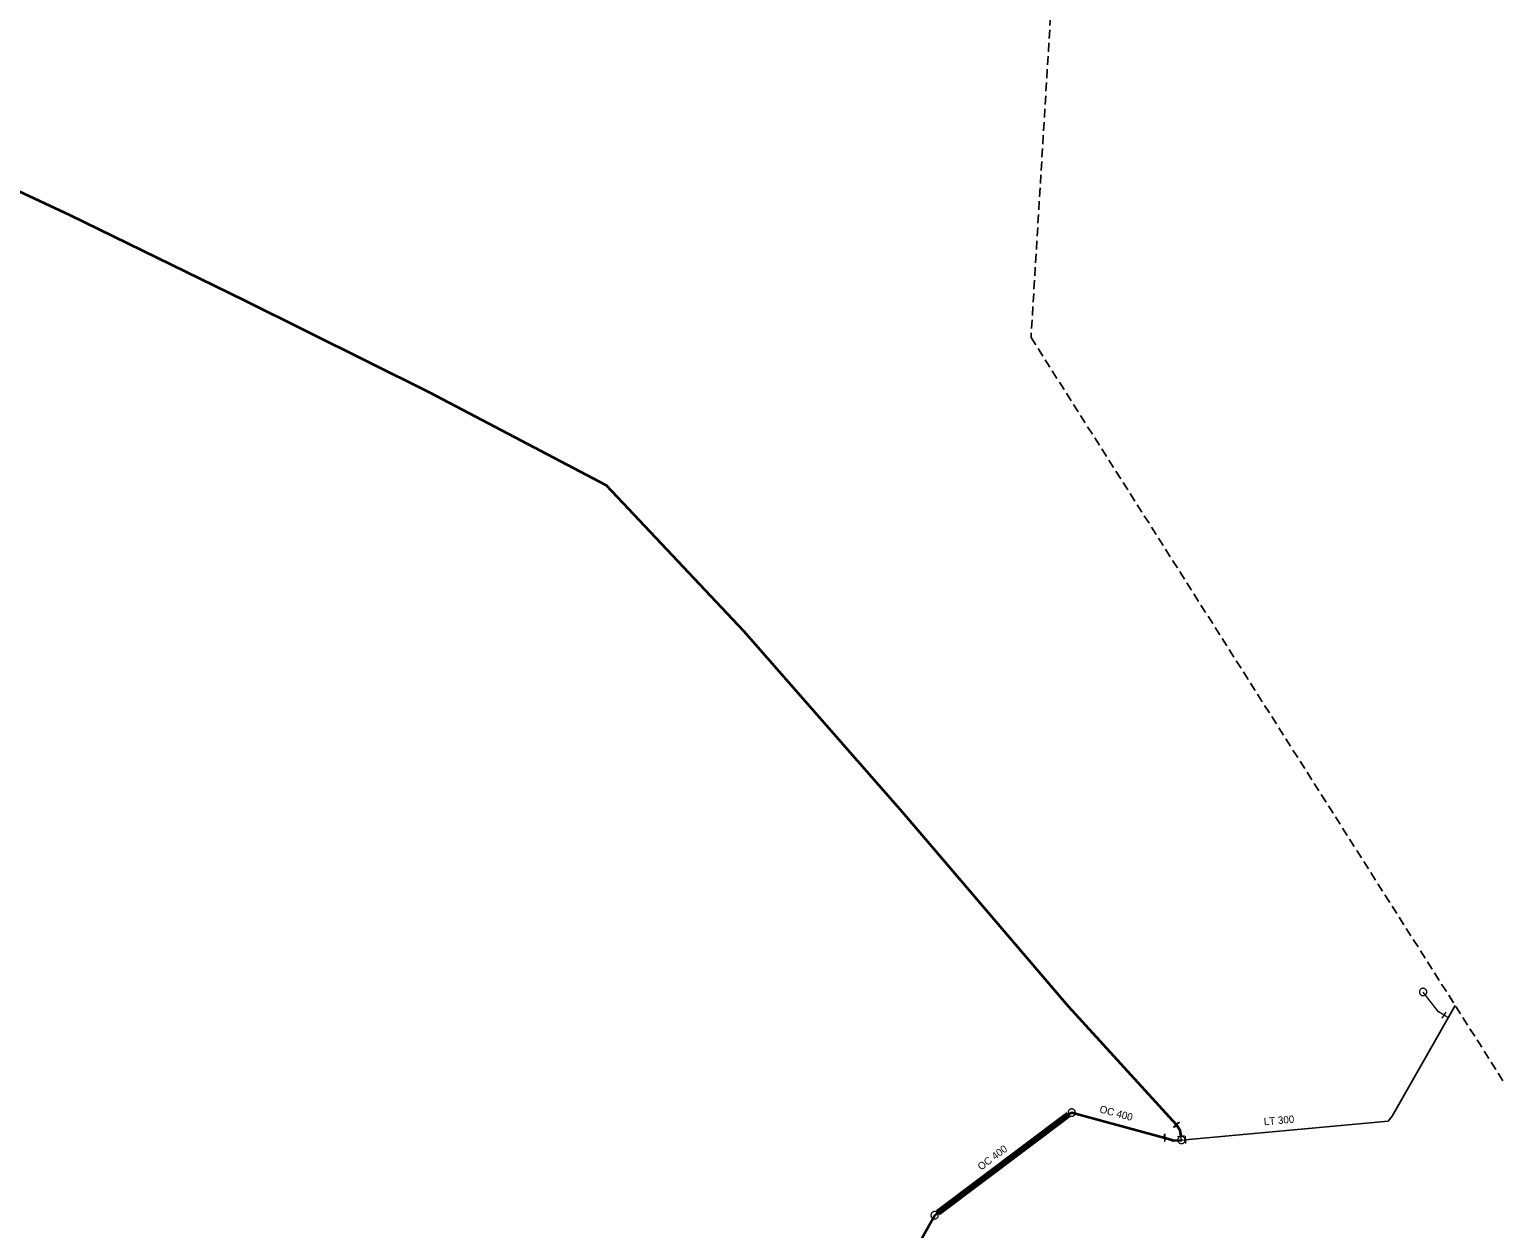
# Model space of a CAD drawing. Extents: x -724325 to -723665, y -972119 to -970722.
# Drawn here: x -724013.1 to -723813.4, y -971291.7 to -971128.2 of the extents above; entities that cross this region are included whole.
import ezdxf

# ---------------------------------------------------------------- set-up
doc = ezdxf.new("R2010")
doc.units = 0
doc.header["$LTSCALE"] = 0.4
doc.linetypes.add('MEDIUM_DASHED', pattern=[4.5, 3, -1.5])
for name, color, linetype, lineweight in [('1', 7, 'Continuous', 25), ('13', 7, 'Continuous', 13), ('14', 7, 'Continuous', 25), ('17', 7, 'Continuous', 35), ('23', 7, 'Continuous', 13), ('3', 7, 'Continuous', 106), ('34', 7, 'Continuous', 13), ('47', 7, 'Continuous', 13)]:
    doc.layers.add(name, color=color, linetype=linetype, lineweight=lineweight)

msp = doc.modelspace()

# ---------------------------------------------------------------- linework, layer by layer
at = {"layer": '1', "linetype": 'MEDIUM_DASHED'}
msp.add_lwpolyline([(-724178.033, -970726.408), (-723849.368, -970722.221), (-723876.582, -971170.211), (-723665.148, -971503.063), (-723686.082, -972118.833), (-723917.752, -972118.833), (-723962.412, -971393.118), (-724325.27, -971133.535)], close=True, dxfattribs=at)
at = {"layer": '13'}
msp.add_lwpolyline([(-723820.26, -971262.559), (-723821.046, -971262.131), (-723823.1, -971259.41)], dxfattribs=at)
at = {"layer": '14', "lineweight": 13}
for p, q in [((-723819.71, -971262.93), (-723820.26, -971262.559)), ((-723856.079, -971279.579), (-723856.14, -971279.03)), ((-723856.079, -971279.579), (-723855.55, -971279.539))]:
    msp.add_line(p, q, dxfattribs=at)
at = {"layer": '17'}
for points in [[(-723856.75, -971277.52), (-723871.469, -971261.379), (-723894.09, -971234.91), (-723915.739, -971210.25), (-723934.449, -971190.379), (-723958.59, -971177.719), (-723983.8, -971165.17), (-724007.629, -971153.55), (-724038.03, -971139.35), (-724069.469, -971127.41), (-724098.62, -971120.079), (-724100.07, -971119.51), (-724120.89, -971115.66), (-724149.294, -971109.225), (-724187.32, -971097.32), (-724220.714, -971087.254), (-724255.679, -971055.409)], [(-723889.699, -971289.809), (-723889.26, -971289.449), (-723871.489, -971276.09), (-723871.01, -971275.82)], [(-723871.01, -971275.82), (-723858.829, -971279.129), (-723858.359, -971279.26)], [(-723856.14, -971279.03), (-723856.17, -971278.77), (-723856.23, -971278.289), (-723856.75, -971277.52)], [(-723858.359, -971279.26), (-723857.5, -971279.51), (-723857.25, -971279.629), (-723856.079, -971279.579)], [(-723897.32, -971301.379), (-723895.809, -971300.579), (-723889.699, -971289.809)]]:
    msp.add_lwpolyline(points, dxfattribs=at)
at = {"layer": '17', "lineweight": 25}
msp.add_lwpolyline([(-723855.55, -971279.539), (-723827.91, -971277.02), (-723827.35, -971276.35), (-723819.71, -971262.93), (-723818.754, -971261.247)], dxfattribs=at)
at = {"layer": '23'}
for points in [[(-723822.793, -971259.031), (-723822.832, -971258.999), (-723822.875, -971258.969), (-723822.924, -971258.946), (-723822.972, -971258.926), (-723823.023, -971258.912), (-723823.074, -971258.903), (-723823.125, -971258.9), (-723823.179, -971258.903), (-723823.229, -971258.91), (-723823.28, -971258.923), (-723823.329, -971258.942), (-723823.376, -971258.965), (-723823.42, -971258.992), (-723823.462, -971259.025), (-723823.5, -971259.062), (-723823.532, -971259.102), (-723823.56, -971259.145), (-723823.585, -971259.192), (-723823.605, -971259.241), (-723823.619, -971259.292), (-723823.627, -971259.343), (-723823.631, -971259.394), (-723823.628, -971259.448), (-723823.621, -971259.499), (-723823.607, -971259.55), (-723823.589, -971259.598), (-723823.566, -971259.645), (-723823.538, -971259.689), (-723823.506, -971259.731), (-723823.469, -971259.769), (-723823.428, -971259.801), (-723823.384, -971259.831), (-723823.339, -971259.855), (-723823.289, -971259.873), (-723823.24, -971259.888), (-723823.189, -971259.897), (-723823.135, -971259.9), (-723823.083, -971259.898), (-723823.031, -971259.89)], [(-723823.627, -971259.343), (-723823.631, -971259.394), (-723823.628, -971259.448), (-723823.621, -971259.499), (-723823.607, -971259.55), (-723823.589, -971259.598), (-723823.566, -971259.645), (-723823.538, -971259.689), (-723823.506, -971259.731), (-723823.469, -971259.769), (-723823.428, -971259.801), (-723823.384, -971259.831), (-723823.339, -971259.855), (-723823.289, -971259.873), (-723823.24, -971259.888), (-723823.189, -971259.897), (-723823.135, -971259.9), (-723823.083, -971259.898), (-723823.031, -971259.89), (-723822.981, -971259.876), (-723822.932, -971259.858), (-723822.885, -971259.836), (-723822.84, -971259.808), (-723822.799, -971259.775), (-723822.763, -971259.738), (-723822.729, -971259.698), (-723822.701, -971259.655), (-723822.677, -971259.607), (-723822.657, -971259.559), (-723822.644, -971259.509), (-723822.634, -971259.458), (-723822.631, -971259.406), (-723822.633, -971259.353), (-723822.641, -971259.3), (-723822.654, -971259.25), (-723822.672, -971259.202), (-723822.694, -971259.155), (-723822.724, -971259.11), (-723822.755, -971259.07), (-723822.793, -971259.031)], [(-723822.885, -971259.836), (-723822.84, -971259.808), (-723822.799, -971259.775), (-723822.763, -971259.738), (-723822.729, -971259.698), (-723822.701, -971259.655), (-723822.677, -971259.607), (-723822.657, -971259.559), (-723822.644, -971259.509), (-723822.634, -971259.458), (-723822.631, -971259.406), (-723822.633, -971259.353), (-723822.641, -971259.3), (-723822.654, -971259.25), (-723822.672, -971259.202), (-723822.694, -971259.155), (-723822.724, -971259.11), (-723822.755, -971259.07), (-723822.793, -971259.031), (-723822.832, -971258.999), (-723822.875, -971258.969), (-723822.924, -971258.946), (-723822.972, -971258.926), (-723823.023, -971258.912), (-723823.074, -971258.903), (-723823.125, -971258.9), (-723823.179, -971258.903), (-723823.229, -971258.91), (-723823.28, -971258.923), (-723823.329, -971258.942), (-723823.376, -971258.965), (-723823.42, -971258.992), (-723823.462, -971259.025), (-723823.5, -971259.062), (-723823.532, -971259.102), (-723823.56, -971259.145), (-723823.585, -971259.192), (-723823.605, -971259.241), (-723823.619, -971259.292), (-723823.627, -971259.343)], [(-723823.031, -971259.89), (-723822.981, -971259.876), (-723822.932, -971259.858), (-723822.885, -971259.836)], [(-723870.533, -971275.837), (-723870.536, -971275.784), (-723870.545, -971275.732), (-723870.56, -971275.683), (-723870.579, -971275.634), (-723870.603, -971275.588), (-723870.633, -971275.544), (-723870.666, -971275.504), (-723870.703, -971275.468), (-723870.744, -971275.435), (-723870.788, -971275.407), (-723870.835, -971275.383), (-723870.885, -971275.365), (-723870.935, -971275.352), (-723870.986, -971275.345), (-723871.038, -971275.342), (-723871.092, -971275.346), (-723871.142, -971275.354), (-723871.194, -971275.369), (-723871.241, -971275.387), (-723871.288, -971275.411), (-723871.332, -971275.442), (-723871.372, -971275.475), (-723871.409, -971275.513), (-723871.442, -971275.553), (-723871.469, -971275.597), (-723871.492, -971275.645), (-723871.51, -971275.693), (-723871.523, -971275.744), (-723871.53, -971275.796), (-723871.533, -971275.848), (-723871.53, -971275.9), (-723871.521, -971275.952), (-723871.507, -971276.003), (-723871.488, -971276.051), (-723871.463, -971276.096), (-723871.434, -971276.14), (-723871.401, -971276.181), (-723871.363, -971276.218), (-723871.322, -971276.25)], [(-723871.194, -971275.369), (-723871.241, -971275.387), (-723871.288, -971275.411), (-723871.332, -971275.442), (-723871.372, -971275.475), (-723871.409, -971275.513), (-723871.442, -971275.553), (-723871.469, -971275.597), (-723871.492, -971275.645), (-723871.51, -971275.693), (-723871.523, -971275.744), (-723871.53, -971275.796), (-723871.533, -971275.848), (-723871.53, -971275.9), (-723871.521, -971275.952), (-723871.507, -971276.003), (-723871.488, -971276.051), (-723871.463, -971276.096), (-723871.434, -971276.14), (-723871.401, -971276.181), (-723871.363, -971276.218), (-723871.322, -971276.25), (-723871.279, -971276.278), (-723871.231, -971276.301), (-723871.183, -971276.32), (-723871.131, -971276.332), (-723871.08, -971276.339), (-723871.028, -971276.342), (-723870.976, -971276.338), (-723870.924, -971276.33), (-723870.873, -971276.316), (-723870.825, -971276.296), (-723870.778, -971276.272), (-723870.735, -971276.244), (-723870.695, -971276.209), (-723870.658, -971276.173), (-723870.626, -971276.132), (-723870.597, -971276.087), (-723870.574, -971276.04), (-723870.556, -971275.991)], [(-723871.322, -971276.25), (-723871.279, -971276.278), (-723871.231, -971276.301), (-723871.183, -971276.32), (-723871.131, -971276.332), (-723871.08, -971276.339), (-723871.028, -971276.342), (-723870.976, -971276.338), (-723870.924, -971276.33), (-723870.873, -971276.316), (-723870.825, -971276.296), (-723870.778, -971276.272), (-723870.735, -971276.244), (-723870.695, -971276.209), (-723870.658, -971276.173), (-723870.626, -971276.132), (-723870.597, -971276.087), (-723870.574, -971276.04), (-723870.556, -971275.991), (-723870.544, -971275.94), (-723870.536, -971275.889), (-723870.533, -971275.837), (-723870.536, -971275.784), (-723870.545, -971275.732), (-723870.56, -971275.683), (-723870.579, -971275.634), (-723870.603, -971275.588), (-723870.633, -971275.544), (-723870.666, -971275.504), (-723870.703, -971275.468), (-723870.744, -971275.435), (-723870.788, -971275.407), (-723870.835, -971275.383), (-723870.885, -971275.365), (-723870.935, -971275.352), (-723870.986, -971275.345), (-723871.038, -971275.342), (-723871.092, -971275.346), (-723871.142, -971275.354), (-723871.194, -971275.369)], [(-723870.556, -971275.991), (-723870.544, -971275.94), (-723870.536, -971275.889), (-723870.533, -971275.837)], [(-723889.223, -971289.827), (-723889.225, -971289.774), (-723889.235, -971289.722), (-723889.25, -971289.673), (-723889.269, -971289.624), (-723889.293, -971289.578), (-723889.323, -971289.534), (-723889.355, -971289.494), (-723889.392, -971289.458), (-723889.434, -971289.425), (-723889.478, -971289.397), (-723889.524, -971289.373), (-723889.575, -971289.355), (-723889.625, -971289.342), (-723889.676, -971289.335), (-723889.728, -971289.332), (-723889.782, -971289.336), (-723889.831, -971289.344), (-723889.884, -971289.359), (-723889.931, -971289.377), (-723889.978, -971289.401), (-723890.022, -971289.432), (-723890.061, -971289.465), (-723890.098, -971289.503), (-723890.132, -971289.543), (-723890.159, -971289.587), (-723890.181, -971289.635), (-723890.2, -971289.683), (-723890.213, -971289.734), (-723890.22, -971289.786), (-723890.223, -971289.838), (-723890.22, -971289.89), (-723890.211, -971289.942), (-723890.196, -971289.993), (-723890.178, -971290.041), (-723890.152, -971290.086), (-723890.124, -971290.13), (-723890.09, -971290.171), (-723890.053, -971290.208), (-723890.012, -971290.24)], [(-723889.884, -971289.359), (-723889.931, -971289.377), (-723889.978, -971289.401), (-723890.022, -971289.432), (-723890.061, -971289.465), (-723890.098, -971289.503), (-723890.132, -971289.543), (-723890.159, -971289.587), (-723890.181, -971289.635), (-723890.2, -971289.683), (-723890.213, -971289.734), (-723890.22, -971289.786), (-723890.223, -971289.838), (-723890.22, -971289.89), (-723890.211, -971289.942), (-723890.196, -971289.993), (-723890.178, -971290.041), (-723890.152, -971290.086), (-723890.124, -971290.13), (-723890.09, -971290.171), (-723890.053, -971290.208), (-723890.012, -971290.24), (-723889.968, -971290.268), (-723889.921, -971290.291), (-723889.872, -971290.31), (-723889.821, -971290.322), (-723889.769, -971290.329), (-723889.718, -971290.332), (-723889.666, -971290.328), (-723889.614, -971290.32), (-723889.563, -971290.306), (-723889.514, -971290.286), (-723889.468, -971290.262), (-723889.424, -971290.234), (-723889.385, -971290.199), (-723889.348, -971290.163), (-723889.316, -971290.122), (-723889.287, -971290.077), (-723889.264, -971290.03), (-723889.245, -971289.981)], [(-723890.012, -971290.24), (-723889.968, -971290.268), (-723889.921, -971290.291), (-723889.872, -971290.31), (-723889.821, -971290.322), (-723889.769, -971290.329), (-723889.718, -971290.332), (-723889.666, -971290.328), (-723889.614, -971290.32), (-723889.563, -971290.306), (-723889.514, -971290.286), (-723889.468, -971290.262), (-723889.424, -971290.234), (-723889.385, -971290.199), (-723889.348, -971290.163), (-723889.316, -971290.122), (-723889.287, -971290.077), (-723889.264, -971290.03), (-723889.245, -971289.981), (-723889.233, -971289.93), (-723889.225, -971289.879), (-723889.223, -971289.827), (-723889.225, -971289.774), (-723889.235, -971289.722), (-723889.25, -971289.673), (-723889.269, -971289.624), (-723889.293, -971289.578), (-723889.323, -971289.534), (-723889.355, -971289.494), (-723889.392, -971289.458), (-723889.434, -971289.425), (-723889.478, -971289.397), (-723889.524, -971289.373), (-723889.575, -971289.355), (-723889.625, -971289.342), (-723889.676, -971289.335), (-723889.728, -971289.332), (-723889.782, -971289.336), (-723889.831, -971289.344), (-723889.884, -971289.359)], [(-723889.245, -971289.981), (-723889.233, -971289.93), (-723889.225, -971289.879), (-723889.223, -971289.827)]]:
    msp.add_lwpolyline(points, dxfattribs=at)
at = {"layer": '3'}
msp.add_line((-723889.26, -971289.45), (-723871.49, -971276.09), dxfattribs=at)
at = {"layer": '3', "lineweight": 100}
msp.add_line((-723889.26, -971289.45), (-723871.49, -971276.09), dxfattribs=at)
at = {"layer": '34'}
for p, q in [((-723820.538, -971262.974), (-723819.98, -971262.144)), ((-723856.636, -971279.084), (-723855.642, -971278.976)), ((-723855.588, -971279.04), (-723855.512, -971280.037))]:
    msp.add_line(p, q, dxfattribs=at)
at = {"layer": '47'}
for p, q in [((-723856.351, -971277.202), (-723856.842, -971277.341)), ((-723858.32, -971278.751), (-723858.552, -971279.206))]:
    msp.add_line(p, q, dxfattribs=at)
for points in [[(-723856.351, -971277.202), (-723857.148, -971277.837), (-723856.657, -971277.698)], [(-723858.32, -971278.751), (-723858.397, -971279.768), (-723858.165, -971279.313)]]:
    msp.add_lwpolyline(points, dxfattribs=at)
for points in [[(-723855.579, -971279.557), (-723855.584, -971279.505), (-723855.594, -971279.454), (-723855.611, -971279.404), (-723855.631, -971279.356), (-723855.657, -971279.31), (-723855.687, -971279.268), (-723855.722, -971279.229), (-723855.761, -971279.194), (-723855.802, -971279.162), (-723855.847, -971279.135), (-723855.895, -971279.113), (-723855.945, -971279.097), (-723855.995, -971279.086), (-723856.048, -971279.08), (-723856.1, -971279.079), (-723856.152, -971279.084), (-723856.203, -971279.094), (-723856.254, -971279.111), (-723856.301, -971279.131), (-723856.347, -971279.157), (-723856.389, -971279.187), (-723856.429, -971279.222), (-723856.464, -971279.261), (-723856.496, -971279.302), (-723856.522, -971279.347), (-723856.544, -971279.395), (-723856.561, -971279.445), (-723856.571, -971279.495), (-723856.577, -971279.548), (-723856.578, -971279.6), (-723856.573, -971279.652), (-723856.563, -971279.703), (-723856.547, -971279.754), (-723856.526, -971279.801), (-723856.5, -971279.847), (-723856.471, -971279.89), (-723856.436, -971279.929), (-723856.397, -971279.964), (-723856.355, -971279.996), (-723856.31, -971280.022), (-723856.262, -971280.044), (-723856.213, -971280.061), (-723856.162, -971280.071), (-723856.109, -971280.077), (-723856.057, -971280.078), (-723856.005, -971280.073), (-723855.954, -971280.063), (-723855.904, -971280.047), (-723855.856, -971280.026), (-723855.81, -971280), (-723855.767, -971279.971), (-723855.729, -971279.936), (-723855.694, -971279.897), (-723855.662, -971279.855), (-723855.635, -971279.81), (-723855.613, -971279.762), (-723855.597, -971279.713), (-723855.586, -971279.662), (-723855.58, -971279.609)], [(-723855.997, -971279.575), (-723855.997, -971279.566), (-723855.999, -971279.558), (-723856.002, -971279.55), (-723856.005, -971279.542), (-723856.009, -971279.535), (-723856.015, -971279.528), (-723856.02, -971279.521), (-723856.026, -971279.515), (-723856.033, -971279.511), (-723856.041, -971279.506), (-723856.049, -971279.502), (-723856.057, -971279.5), (-723856.065, -971279.498), (-723856.073, -971279.496), (-723856.082, -971279.497), (-723856.091, -971279.497), (-723856.099, -971279.499), (-723856.107, -971279.502), (-723856.115, -971279.505), (-723856.122, -971279.509), (-723856.129, -971279.515), (-723856.136, -971279.52), (-723856.142, -971279.526), (-723856.147, -971279.533), (-723856.151, -971279.541), (-723856.155, -971279.549), (-723856.157, -971279.557), (-723856.159, -971279.565), (-723856.161, -971279.573), (-723856.16, -971279.582), (-723856.16, -971279.591), (-723856.158, -971279.599), (-723856.155, -971279.607), (-723856.152, -971279.615), (-723856.148, -971279.622), (-723856.143, -971279.629), (-723856.137, -971279.636), (-723856.131, -971279.642), (-723856.124, -971279.647), (-723856.116, -971279.651), (-723856.108, -971279.655), (-723856.1, -971279.657), (-723856.092, -971279.659), (-723856.084, -971279.661), (-723856.075, -971279.66), (-723856.066, -971279.66), (-723856.058, -971279.658), (-723856.05, -971279.655), (-723856.042, -971279.652), (-723856.035, -971279.648), (-723856.028, -971279.643), (-723856.021, -971279.637), (-723856.015, -971279.631), (-723856.011, -971279.624), (-723856.006, -971279.616), (-723856.002, -971279.608), (-723856, -971279.6), (-723855.998, -971279.592), (-723855.996, -971279.584)]]:
    msp.add_lwpolyline(points, close=True, dxfattribs=at)

# ---------------------------------------------------------------- texts
at = {"layer": '1'}
for s, rotation, p in [('OC 400', 345, (-723867.32, -971275.799)), ('LT 300', 5, (-723844.806, -971277.57)), ('OC 400', 37, (-723883.389, -971283.766))]:
    msp.add_text(s, height=1, rotation=rotation, dxfattribs=at).set_placement(p)

doc.saveas('drawing.dxf')
